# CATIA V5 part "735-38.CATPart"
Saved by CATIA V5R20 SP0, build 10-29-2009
Part number: 735-38
Bounding box of the stored display mesh (mm): x -33 to 33, y -32.999 to 32.999, z -37 to 45
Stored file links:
  C:\Users\Utente\Desktop\IO LAVORO\3D X SITO CF\X SITO\735\735-38.CATPart
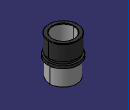
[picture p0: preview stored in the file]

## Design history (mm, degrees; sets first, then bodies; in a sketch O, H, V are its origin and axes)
Set1
  DatumSurface1 to DatumSurface25 "735-38"
Body1 (main body)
